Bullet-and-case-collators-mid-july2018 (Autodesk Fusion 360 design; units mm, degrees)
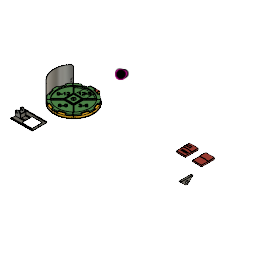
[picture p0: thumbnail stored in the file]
named bodies: "mk1j-bullet-base-feeder-beta", "mk1b-nose-guide", "mk1-flip-ramp", "mk1d-nose-guide-spacer", "mk2b-collator-plate-223", "mk1L-case-feeder-base-6-9", "mk1b-obsolete-case-feeder-base-centre", "mk1c-base-plate-attach", "mk1-case-to-pole-top", "mk1c-base-to-slinky flange", "mk1j-base-wall-beta", "mk1L-case-feeder-base-9-12", "mk1L-case-feeder-base-12-3", "mk2d-case-feeder-centre-motor", "mk1b-case-side-6-9", "mk1b-case-side-3-6", "mk1c-case-side-9-12", "mk1e-case-collator-223-centre", "mk1e-case-plate-223-6-9", "mk1e-case-plate-223-9-12", "mk1e-case-plate-223-12-3", "mk1e-case-plate-223-3-6", "mk1b-bullet-steady-spring", "mk1d-lh-45deg-leg", "mk1d-rh-45deg-leg", "mk2b-recessed-collator-plate-223", "mk2c8-plus8mm-recessed-collator-plate-223", "mk2d-55gr-70deg-4mm-collator-plate-223", "mk1c-leg-rh-feet-extended", "mk1-original-flip-ramp (1)", "mk2-flip-ramp", "mk1b-nose-guide-spacer", "mk2g-62gr-70deg-3mm-collator-plate-223-beta", "mk2e-ii-62gr-70deg-4mm-collator-plate-223", "mk1-inside-scraper", "mk1-wall-9-12-case", "mk1c-wall-6-9-case", "mk1b-wall-3-6-case", "mk1d-case-fulcrum-223", "mk1b-case-shoot", "mk2b-plus-2mm-flip-ramp", "mk2b-plus-2mm-narrow-flip-ramp", "mk1c-leg-lh-feet-extended", "mk1c-leg-rh-feet-extended (1)", "mk1c-leg-rh-feet-extended (2)", "mk1b-bullet-collator-bench-stand-bottom", "mk1h-control-case-base", "mk1h-control-case-top", "mk1b-dowel-clamp", "mk1b-bullet-support-bracket", "mk1b-bullet-stand-top", "mk1g-case-feeder-base-9-12 (1)", "mk1g-case-feeder-base-6-9 (1)", "mk1g-case-feeder-base-3-6 (1)", "mk1L-case-feeder-base-3-6", "mk1b-9-12-6-9-wall-joiner", "mk1b-3-6-6-9-wall-joiner", "mk1b-case-guide-wall-joiner", "mk1b-case-feeder-test-base", "mk3b-223-case-shute"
